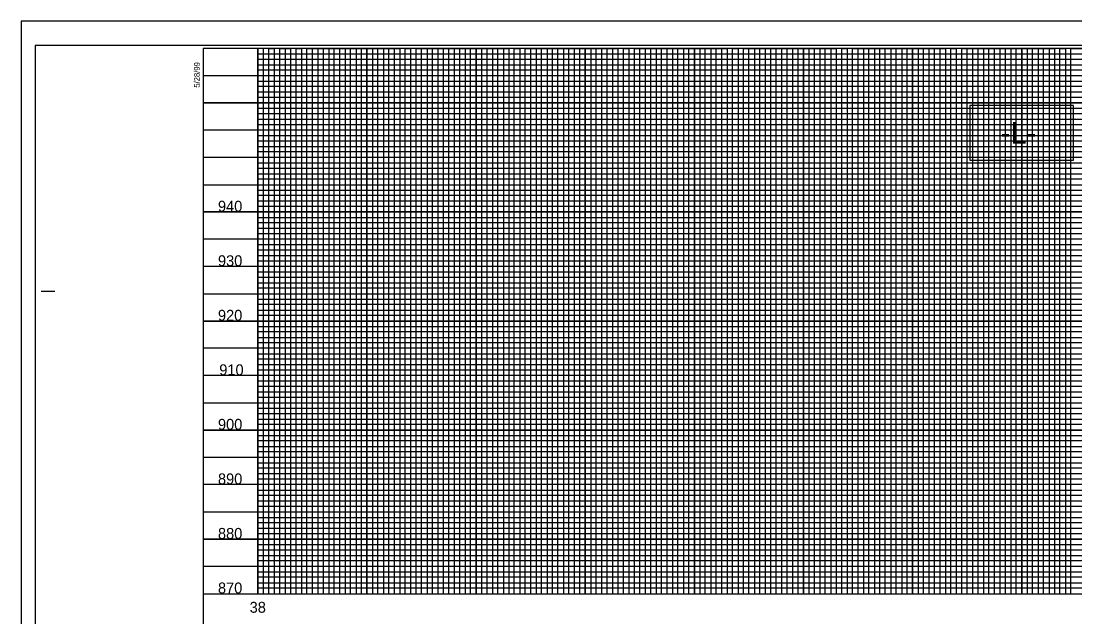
# Model space of a CAD drawing. Extents: x 1648649 to 1651827, y 844691 to 845879.
# Drawn here: x 1649962 to 1650928, y 845245 to 845791 of the extents above; entities that cross this region are included whole.
import ezdxf

# ---------------------------------------------------------------- set-up
doc = ezdxf.new("R2010")
doc.units = 0
for name, color, linetype in [('Exist Vertical Profile Horizontal Axis Label Major', 7, 'Continuous'), ('Exist Vertical Profile Vertical Axis Label', 7, 'Continuous'), ('Prop Grid Mask', 7, 'Continuous'), ('Sheet Cutting Line CELL', 7, 'Continuous'), ('Sheet DOT Grid CELL', 7, 'Continuous'), ('Sheet Plot Border Inside CELL', 7, 'Continuous'), ('Sheet Plot Border Outside CELL', 7, 'Continuous'), ('Sheet Profile CELL', 7, 'Continuous'), ('Sheet Profile Grid Major CELL', 7, 'Continuous'), ('Sheet Profile Grid Middle CELL', 7, 'Continuous'), ('Sheet Profile Grid Minor CELL', 7, 'Continuous')]:
    doc.layers.add(name, color=color, linetype=linetype)

msp = doc.modelspace()

# ---------------------------------------------------------------- linework, layer by layer
at = {"layer": 'Prop Grid Mask'}
msp.add_lwpolyline([(1650831.78, 845713.52), (1650831.78, 845663.52), (1650926.78, 845663.52), (1650926.78, 845713.52)], close=True, dxfattribs=at)
at = {"layer": 'Sheet Cutting Line CELL'}
for p, q in [((1651646.28, 845791.02), (1649962.28, 845791.02)), ((1649962.28, 845791.02), (1649962.28, 844691.02))]:
    msp.add_line(p, q, dxfattribs=at)
at = {"layer": 'Sheet DOT Grid CELL'}
for p, q in [((1650179.28, 845266.02), (1650179.28, 845766.02)), ((1650179.28, 845266.02), (1650179.28, 845766.02)), ((1650229.28, 845266.02), (1650229.28, 845766.02)), ((1650229.28, 845266.02), (1650229.28, 845766.02)), ((1650279.28, 845266.02), (1650279.28, 845766.02)), ((1650279.28, 845266.02), (1650279.28, 845766.02)), ((1650329.28, 845266.02), (1650329.28, 845766.02)), ((1650329.28, 845266.02), (1650329.28, 845766.02)), ((1650379.28, 845266.02), (1650379.28, 845766.02)), ((1650379.28, 845266.02), (1650379.28, 845766.02)), ((1650429.28, 845266.02), (1650429.28, 845766.02)), ((1650429.28, 845266.02), (1650429.28, 845766.02)), ((1650479.28, 845266.02), (1650479.28, 845766.02)), ((1650479.28, 845266.02), (1650479.28, 845766.02)), ((1650529.28, 845266.02), (1650529.28, 845766.02)), ((1650529.28, 845266.02), (1650529.28, 845766.02)), ((1650579.28, 845266.02), (1650579.28, 845766.02)), ((1650579.28, 845266.02), (1650579.28, 845766.02)), ((1650629.28, 845266.02), (1650629.28, 845766.02)), ((1650629.28, 845266.02), (1650629.28, 845766.02)), ((1650679.28, 845266.02), (1650679.28, 845766.02)), ((1650679.28, 845266.02), (1650679.28, 845766.02)), ((1650729.28, 845266.02), (1650729.28, 845766.02)), ((1650729.28, 845266.02), (1650729.28, 845766.02)), ((1650779.28, 845266.02), (1650779.28, 845766.02)), ((1650779.28, 845266.02), (1650779.28, 845766.02)), ((1650829.28, 845266.02), (1650829.28, 845766.02)), ((1650829.28, 845266.02), (1650829.28, 845766.02)), ((1650879.28, 845266.02), (1650879.28, 845766.02)), ((1650879.28, 845266.02), (1650879.28, 845766.02)), ((1651429.23, 845716.02), (1650129.28, 845716.02)), ((1651429.23, 845716.02), (1650129.28, 845716.02)), ((1651429.23, 845666.02), (1650129.28, 845666.02)), ((1651429.23, 845666.02), (1650129.28, 845666.02)), ((1651429.28, 845616.02), (1650129.28, 845616.02)), ((1651429.28, 845616.02), (1650129.28, 845616.02)), ((1651629.28, 845566.02), (1650129.28, 845566.02)), ((1651629.28, 845566.02), (1650129.28, 845566.02)), ((1651629.28, 845516.02), (1650129.28, 845516.02)), ((1651629.28, 845516.02), (1650129.28, 845516.02)), ((1651629.28, 845466.02), (1650129.28, 845466.02)), ((1651629.28, 845466.02), (1650129.28, 845466.02)), ((1651629.28, 845416.02), (1650129.28, 845416.02)), ((1651629.28, 845416.02), (1650129.28, 845416.02)), ((1651629.28, 845366.02), (1650129.28, 845366.02)), ((1651629.28, 845366.02), (1650129.28, 845366.02)), ((1651629.28, 845316.02), (1650129.28, 845316.02)), ((1651629.28, 845316.02), (1650129.28, 845316.02))]:
    msp.add_line(p, q, dxfattribs=at)
at = {"layer": 'Sheet Plot Border Inside CELL'}
msp.add_lwpolyline([(1649975.28, 844713.47), (1651641.78, 844713.47), (1651641.78, 845768.57), (1649975.28, 845768.57)], close=True, dxfattribs=at)
at = {"layer": 'Sheet Plot Border Outside CELL'}
msp.add_lwpolyline([(1649962.28, 844691.02), (1651646.28, 844691.02), (1651646.28, 845791.02), (1649962.28, 845791.02)], close=True, dxfattribs=at)
at = {"layer": 'Sheet Profile CELL'}
for p, q in [((1649980.78, 845543.52), (1649993.28, 845543.52)), ((1650129.28, 845266.02), (1651629.28, 845266.02))]:
    msp.add_line(p, q, dxfattribs=at)
msp.add_lwpolyline([(1651629.28, 845766.02), (1650129.28, 845766.02), (1650129.28, 844716.02), (1651629.28, 844716.02)], close=True, dxfattribs=at)
at = {"layer": 'Sheet Profile Grid Major CELL'}
for points in [[(1650179.28, 845766.02), (1650179.28, 845266.02), (1650229.28, 845266.02), (1650229.28, 845766.02), (1650279.28, 845766.02), (1650279.28, 845266.02), (1650329.28, 845266.02), (1650329.28, 845766.02), (1650379.28, 845766.02), (1650379.28, 845266.02), (1650429.28, 845266.02), (1650429.28, 845766.02), (1650479.28, 845766.02), (1650479.28, 845266.02), (1650529.28, 845266.02), (1650529.28, 845766.02), (1650579.28, 845766.02), (1650579.28, 845266.02), (1650629.28, 845266.02), (1650629.28, 845766.02), (1650679.28, 845766.02), (1650679.28, 845266.02), (1650729.28, 845266.02), (1650729.28, 845766.02), (1650779.28, 845766.02), (1650779.28, 845266.02), (1650829.28, 845266.02), (1650829.28, 845766.02), (1650879.28, 845766.02), (1650879.28, 845266.02), (1650929.28, 845266.02)], [(1650129.28, 845716.02), (1651429.28, 845716.02)], [(1651429.28, 845666.02), (1650129.28, 845666.02), (1650129.28, 845616.02), (1651429.28, 845616.02)], [(1651629.28, 845566.02), (1650129.28, 845566.02), (1650129.28, 845516.02), (1651629.28, 845516.02)], [(1651629.28, 845466.02), (1650129.28, 845466.02), (1650129.28, 845416.02), (1651629.28, 845416.02)], [(1651629.28, 845366.02), (1650129.28, 845366.02), (1650129.28, 845366.02), (1650129.28, 845316.02), (1651629.28, 845316.02)]]:
    msp.add_lwpolyline(points, dxfattribs=at)
at = {"layer": 'Sheet Profile Grid Middle CELL'}
msp.add_line((1650129.28, 845741.02), (1651279.28, 845741.02), dxfattribs=at)
for points in [[(1650204.28, 845766.02), (1650204.28, 845266.02), (1650254.28, 845266.02), (1650254.28, 845766.02), (1650304.28, 845766.02), (1650304.28, 845266.02), (1650354.28, 845266.02), (1650354.28, 845766.02), (1650404.28, 845766.02), (1650404.28, 845266.02), (1650454.28, 845266.02), (1650454.28, 845766.02), (1650504.28, 845766.02), (1650504.28, 845266.02), (1650554.28, 845266.02), (1650554.28, 845766.02), (1650604.28, 845766.02), (1650604.28, 845266.02), (1650654.28, 845266.02), (1650654.28, 845766.02), (1650704.28, 845766.02), (1650704.28, 845266.02), (1650754.28, 845266.02), (1650754.28, 845266.02), (1650754.28, 845766.02), (1650804.28, 845766.02), (1650804.28, 845266.02), (1650854.28, 845266.02), (1650854.28, 845766.02), (1650904.28, 845766.02), (1650904.28, 845266.02), (1650954.28, 845266.02)], [(1651429.28, 845691.02), (1650129.28, 845691.02), (1650129.28, 845641.02), (1651429.28, 845641.02)], [(1651629.28, 845591.02), (1650129.28, 845591.02), (1650129.28, 845541.02), (1651454.28, 845541.02)], [(1651629.28, 845491.02), (1650129.28, 845491.02), (1650129.28, 845441.02), (1651629.28, 845441.02)], [(1651629.28, 845391.02), (1650129.28, 845391.02), (1650129.28, 845341.02), (1651629.28, 845341.02)], [(1651629.28, 845291.02), (1650129.28, 845291.02)]]:
    msp.add_lwpolyline(points, dxfattribs=at)
at = {"layer": 'Sheet Profile Grid Minor CELL'}
for p, q in [((1650179.28, 845761.02), (1651279.28, 845761.02)), ((1650179.28, 845756.02), (1650179.28, 845756.02)), ((1650179.28, 845756.02), (1650179.28, 845756.02)), ((1650179.28, 845756.02), (1650179.28, 845756.02)), ((1651279.28, 845755.98), (1650179.28, 845755.67)), ((1650179.28, 845751.02), (1651279.28, 845751.02)), ((1651429.23, 845631.02), (1650179.28, 845631.02)), ((1651429.28, 845626.02), (1650179.28, 845626.02)), ((1651429.28, 845621.02), (1650179.28, 845621.02)), ((1650179.28, 845611.02), (1651429.28, 845611.02)), ((1651429.28, 845606.02), (1650179.28, 845606.02)), ((1650179.28, 845601.02), (1651579.28, 845601.02)), ((1651579.28, 845581.02), (1650179.28, 845581.02)), ((1650179.28, 845576.02), (1651579.28, 845576.02)), ((1651579.28, 845556.02), (1650179.28, 845556.02)), ((1650179.28, 845551.02), (1651579.28, 845551.02)), ((1651579.28, 845531.02), (1650179.28, 845531.02)), ((1650179.28, 845526.02), (1651579.28, 845526.02)), ((1651579.28, 845521.02), (1650179.28, 845521.02)), ((1650179.28, 845511.02), (1651579.28, 845511.02)), ((1651579.28, 845506.02), (1650179.28, 845506.02)), ((1650179.28, 845501.02), (1651579.28, 845501.02)), ((1651579.28, 845496.02), (1650179.28, 845496.02)), ((1650179.28, 845486.02), (1651579.28, 845486.02)), ((1651579.28, 845481.02), (1650179.28, 845481.02)), ((1650179.28, 845476.02), (1651579.28, 845476.02)), ((1651579.28, 845471.02), (1650179.28, 845471.02)), ((1650179.28, 845461.02), (1651579.28, 845461.02)), ((1651579.28, 845456.02), (1650179.28, 845456.02)), ((1650179.28, 845451.02), (1651579.28, 845451.02)), ((1651579.28, 845446.02), (1650179.28, 845446.02)), ((1650179.28, 845436.02), (1651579.28, 845436.02)), ((1651579.28, 845431.02), (1650179.28, 845431.02)), ((1650179.28, 845426.02), (1651579.28, 845426.02)), ((1651579.28, 845421.02), (1650179.28, 845421.02)), ((1650179.28, 845411.02), (1651579.28, 845411.02)), ((1651579.28, 845406.02), (1650179.28, 845406.02)), ((1650179.28, 845401.02), (1651579.28, 845401.02)), ((1651579.28, 845396.02), (1650179.28, 845396.02)), ((1650179.28, 845386.02), (1651579.28, 845386.02)), ((1651579.28, 845381.02), (1650179.28, 845381.02)), ((1651579.28, 845376.02), (1650179.28, 845376.02)), ((1651579.28, 845371.02), (1650179.28, 845371.02)), ((1650179.28, 845361.02), (1651579.28, 845361.02)), ((1651579.28, 845356.02), (1650179.28, 845356.02)), ((1650179.28, 845351.02), (1651579.28, 845351.02)), ((1651579.28, 845346.02), (1650179.28, 845346.02)), ((1650179.28, 845336.02), (1651579.28, 845336.02)), ((1651579.28, 845331.02), (1650179.28, 845331.02)), ((1650179.28, 845326.02), (1651579.28, 845326.02)), ((1651579.28, 845321.02), (1650179.28, 845321.02)), ((1650179.28, 845311.02), (1651579.28, 845311.02)), ((1651579.28, 845306.02), (1650179.28, 845306.02)), ((1650179.28, 845301.02), (1651579.28, 845301.02)), ((1651579.28, 845296.02), (1650179.28, 845296.02)), ((1650179.28, 845286.02), (1651579.28, 845286.02)), ((1651579.28, 845281.02), (1650179.28, 845281.02)), ((1650179.28, 845276.02), (1651579.28, 845276.02))]:
    msp.add_line(p, q, dxfattribs=at)
for points in [[(1650184.28, 845766.02), (1650184.28, 845266.02), (1650189.28, 845266.02), (1650189.28, 845766.02), (1650194.28, 845766.02), (1650194.28, 845266.02), (1650199.28, 845266.02), (1650199.28, 845766.02), (1650209.28, 845766.02), (1650209.28, 845266.02), (1650214.28, 845266.02), (1650214.28, 845766.02), (1650219.28, 845766.02), (1650219.28, 845266.02), (1650224.28, 845266.02), (1650234.28, 845266.02), (1650239.28, 845266.02), (1650239.28, 845766.02), (1650244.28, 845766.02), (1650244.28, 845266.02), (1650249.28, 845266.02), (1650249.28, 845766.02), (1650259.28, 845766.02), (1650259.28, 845266.02), (1650264.28, 845266.02), (1650264.28, 845766.02), (1650269.28, 845766.02), (1650269.28, 845266.02), (1650274.28, 845266.02), (1650274.28, 845766.02), (1650284.28, 845766.02), (1650284.28, 845266.02), (1650289.28, 845266.02), (1650289.28, 845766.02), (1650294.28, 845766.02), (1650294.28, 845266.02), (1650299.28, 845266.02), (1650299.28, 845766.02), (1650309.28, 845766.02), (1650309.28, 845266.02), (1650314.28, 845266.02), (1650314.28, 845766.02), (1650319.28, 845766.02), (1650319.28, 845266.02), (1650324.28, 845266.02), (1650324.28, 845766.02), (1650334.28, 845766.02), (1650334.28, 845266.02), (1650339.28, 845266.02), (1650339.28, 845766.02), (1650344.28, 845766.02), (1650344.28, 845266.02), (1650349.28, 845266.02), (1650349.28, 845766.02), (1650359.28, 845766.02), (1650359.28, 845266.02), (1650364.28, 845266.02), (1650364.28, 845766.02), (1650369.28, 845766.02), (1650369.28, 845266.02), (1650374.28, 845266.02), (1650374.28, 845766.02), (1650384.28, 845766.02), (1650384.28, 845266.02), (1650389.28, 845266.02), (1650389.28, 845766.02), (1650394.28, 845766.02), (1650394.28, 845266.02)], [(1650224.28, 845266.02), (1650224.28, 845766.02), (1650234.28, 845766.02), (1650234.28, 845266.02)], [(1650394.28, 845266.02), (1650399.28, 845266.02), (1650399.28, 845766.02), (1650409.28, 845766.02), (1650409.28, 845266.02), (1650414.28, 845266.02), (1650414.28, 845766.02), (1650419.28, 845766.02), (1650419.28, 845266.02), (1650424.28, 845266.02), (1650424.28, 845766.02), (1650434.28, 845766.02), (1650434.28, 845266.02), (1650439.28, 845266.02), (1650439.28, 845766.02), (1650444.28, 845766.02), (1650444.28, 845266.02), (1650449.28, 845266.02), (1650449.28, 845766.02), (1650459.28, 845766.02), (1650459.28, 845266.02), (1650464.28, 845266.02), (1650464.28, 845766.02), (1650469.28, 845766.02), (1650469.28, 845266.02), (1650474.28, 845266.02), (1650474.28, 845766.02), (1650484.28, 845766.02), (1650484.28, 845266.02), (1650489.28, 845266.02), (1650489.28, 845766.02), (1650494.28, 845766.02), (1650494.28, 845266.02), (1650499.28, 845266.02), (1650499.28, 845766.02), (1650509.28, 845766.02), (1650509.28, 845266.02), (1650514.28, 845266.02), (1650514.28, 845766.02), (1650519.28, 845766.02), (1650519.28, 845266.02), (1650524.28, 845266.02), (1650524.28, 845766.02), (1650534.28, 845766.02), (1650534.28, 845266.02), (1650539.28, 845266.02), (1650539.28, 845766.02), (1650544.28, 845766.02), (1650544.28, 845266.02), (1650549.28, 845266.02), (1650549.28, 845766.02), (1650559.28, 845766.02), (1650559.28, 845266.02), (1650564.28, 845266.02), (1650564.28, 845766.02), (1650569.28, 845766.02), (1650569.28, 845266.02), (1650574.28, 845266.02), (1650574.28, 845766.02), (1650584.28, 845766.02), (1650584.28, 845266.02), (1650589.28, 845266.02), (1650589.28, 845766.02), (1650594.28, 845766.02), (1650594.28, 845266.02), (1650599.28, 845266.02), (1650599.28, 845766.02), (1650609.28, 845766.02), (1650609.28, 845266.02), (1650614.28, 845266.02), (1650614.28, 845766.02), (1650619.28, 845766.02), (1650619.28, 845266.02), (1650624.28, 845266.02), (1650624.28, 845766.02), (1650634.28, 845766.02), (1650634.28, 845266.02), (1650639.28, 845266.02), (1650639.28, 845766.02), (1650644.28, 845766.02), (1650644.28, 845266.02), (1650649.28, 845266.02), (1650649.28, 845766.02), (1650659.28, 845766.02), (1650659.28, 845266.02), (1650664.28, 845266.02), (1650664.28, 845766.02), (1650669.28, 845766.02), (1650669.28, 845266.02), (1650674.28, 845266.02), (1650674.28, 845766.02), (1650684.28, 845766.02), (1650684.28, 845266.02), (1650689.28, 845266.02), (1650689.28, 845766.02), (1650694.28, 845766.02), (1650694.28, 845266.02), (1650699.28, 845266.02), (1650699.28, 845766.02), (1650709.28, 845766.02)], [(1650709.28, 845766.02), (1650709.28, 845266.02), (1650714.28, 845266.02), (1650714.28, 845766.02), (1650719.28, 845766.02), (1650719.28, 845266.02), (1650724.28, 845266.02), (1650724.28, 845766.02), (1650734.28, 845766.02), (1650734.28, 845266.02), (1650739.28, 845266.02), (1650739.28, 845766.02), (1650744.28, 845766.02), (1650744.28, 845266.02), (1650749.28, 845266.02), (1650749.28, 845766.02), (1650759.28, 845766.02), (1650759.28, 845266.02), (1650764.28, 845266.02), (1650764.28, 845766.02), (1650769.28, 845766.02), (1650769.28, 845266.02), (1650774.28, 845266.02), (1650774.28, 845766.02), (1650784.28, 845766.02), (1650784.28, 845266.02), (1650789.28, 845266.02), (1650789.28, 845766.02), (1650794.28, 845766.02), (1650794.28, 845266.02), (1650799.28, 845266.02), (1650799.28, 845766.02), (1650809.28, 845766.02), (1650809.28, 845266.02), (1650814.28, 845266.02), (1650814.28, 845766.02), (1650819.28, 845766.02), (1650819.28, 845266.02), (1650824.28, 845266.02), (1650824.28, 845766.02), (1650834.28, 845766.02), (1650834.28, 845266.02), (1650834.28, 845266.02), (1650839.28, 845266.02), (1650839.28, 845766.02), (1650844.28, 845766.02), (1650844.28, 845266.02), (1650849.28, 845266.02), (1650849.28, 845766.02), (1650859.28, 845766.02), (1650859.28, 845266.02), (1650864.28, 845266.02), (1650864.28, 845766.02), (1650869.28, 845766.02), (1650869.28, 845266.02), (1650874.28, 845266.02), (1650874.28, 845766.02), (1650884.28, 845766.02), (1650884.28, 845266.02), (1650889.28, 845266.02), (1650889.28, 845766.02), (1650894.28, 845766.02), (1650894.28, 845266.02), (1650899.28, 845266.02), (1650899.28, 845766.02), (1650909.28, 845766.02), (1650909.28, 845266.02), (1650914.28, 845266.02), (1650914.28, 845766.02), (1650919.28, 845766.02), (1650919.28, 845266.02), (1650924.28, 845266.02), (1650924.28, 845766.02), (1650934.28, 845766.02)], [(1651279.28, 845746.02), (1650179.28, 845746.02), (1650179.28, 845736.02), (1651429.28, 845736.02)], [(1651429.23, 845731.02), (1650179.28, 845731.02), (1650179.28, 845726.02), (1651429.28, 845726.02)], [(1651429.28, 845721.02), (1650179.28, 845721.02), (1650179.28, 845711.02), (1651429.28, 845711.02)], [(1651429.28, 845706.02), (1650179.28, 845706.02), (1650179.28, 845701.02), (1651429.28, 845701.02)], [(1651429.28, 845696.02), (1650179.28, 845696.02), (1650179.28, 845686.02), (1651429.28, 845686.02)], [(1651429.28, 845681.02), (1650179.28, 845681.02), (1650179.28, 845676.02), (1651429.28, 845676.02)], [(1651429.28, 845671.02), (1650179.28, 845671.02), (1650179.28, 845661.02), (1651429.28, 845661.02)], [(1651429.28, 845655.92), (1650179.38, 845655.92), (1650179.38, 845651.02), (1651429.28, 845651.02)], [(1651429.28, 845646.02), (1650179.28, 845646.02), (1650179.28, 845636.02), (1651429.28, 845636.02)], [(1651579.28, 845596.02), (1650179.28, 845596.02), (1650179.28, 845586.02), (1651579.28, 845586.02)], [(1651579.28, 845571.02), (1650179.28, 845571.02), (1650179.28, 845561.02), (1651579.28, 845561.02)], [(1651579.28, 845546.02), (1650179.28, 845546.02), (1650179.28, 845536.02), (1651579.28, 845536.02)], [(1651579.28, 845271.02), (1650179.28, 845271.02)]]:
    msp.add_lwpolyline(points, dxfattribs=at)

# ---------------------------------------------------------------- texts
at = {"layer": 'Exist Vertical Profile Horizontal Axis Label Major'}
for s, height, p in [('-L-', 20, (1650860.04, 845678.52)), ('38', 10, (1650171.75, 845248.52))]:
    msp.add_text(s, height=height, dxfattribs=at).set_placement(p)
at = {"layer": 'Exist Vertical Profile Vertical Axis Label'}
for s, p in [('940', (1650142.71, 845616.27)), ('930', (1650142.71, 845566.27)), ('920', (1650142.71, 845516.27)), ('910', (1650143.91, 845466.27)), ('900', (1650142.71, 845416.27)), ('890', (1650142.71, 845366.27)), ('880', (1650142.71, 845316.27)), ('870', (1650142.71, 845266.27))]:
    msp.add_text(s, height=10, dxfattribs=at).set_placement(p)
at = {"layer": 'Sheet Profile CELL'}
msp.add_text('5/28/99', height=5.25, rotation=90, dxfattribs=at).set_placement((1650126.04, 845729.94))

doc.saveas('drawing.dxf')
